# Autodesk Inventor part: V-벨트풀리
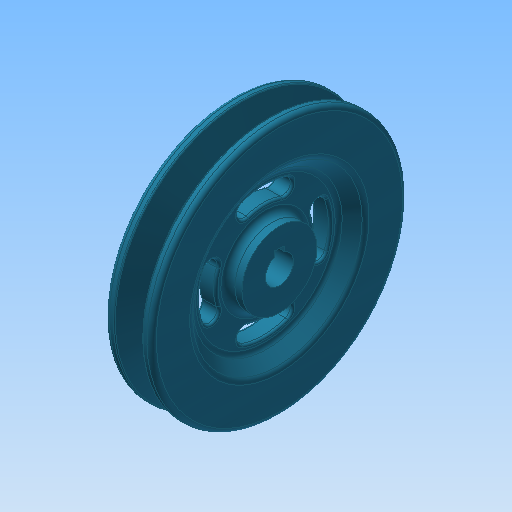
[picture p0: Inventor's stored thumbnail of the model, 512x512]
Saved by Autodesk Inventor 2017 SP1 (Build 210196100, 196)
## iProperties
Created: 2015-12
Part Number: V-벨트풀리
Document SubType Name: Modeling
Designer: mdu
Density: 8.08 g/cm^3
Material: 스테인리스강
Mass: 919.289 g
Surface Area: 326.109 cm^2
Volume: 113.773 cm^3
Appearance: 터키옥색
Author: mdu
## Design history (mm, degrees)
sketch "스케치1"
  geometry: L1 (-10, 0)-(10, 0); L2 (-10, 0)-(-10, 16); L3 (-10, 16)-(-4, 16); L4 (-4, 16)-(-4, 31); L5 (-4, 31)-(-10, 37); L6 (-10, 37)-(-10, 54.5); L7 (-10, 54.5)-(-5.976, 54.5); L8 (-5.976, 54.5)-(-2.154, 42); L9 (-2.154, 42)-(2.154, 42); L10 (2.154, 42)-(5.976, 54.5); L11 (5.976, 54.5)-(10, 54.5); L12 (10, 54.5)-(10, 37); L13 (10, 37)-(4, 31); L14 (4, 31)-(4, 16); L15 (4, 16)-(10, 16); L16 (10, 16)-(10, 0); L17 (-4.6, 50)-(4.6, 50); 2 further points
  constraints: 34 end point, 7 parallel, 6 equal length, 5 collinear, 3 perpendicular, 2 point on line, 1 coincident, 1 horizontal, 1 midpoint
  dimensions: "d0" = 20 distance of L1.start L1.end; "d1" = 9.2 distance of L17.start L17.end; "d2" = 34 deg angle of L10 L8; "d3" = 4.5 distance between parallel lines of L7 L17; "d4" = 8 distance between parallel lines of L9 L17; "d6" = 100 diameter of L17 L1; "d7" = 32 diameter of L3 L1; "d8" = 74 diameter of L5.end L1; "d9" = 6 distance of L2.end L3.end; "d10" = 135 deg angle of L4 L5
revolve "회전1" sketch "스케치1" stored, may be unused: angle "d11" = 90 deg
fillet "모깎기1" dims "d12" = 2, "d13" = 0.5, "d14" = 1, "d15" = 3
sketch "스케치2"
  geometry: L1 (-2, 5.657)-(-2, 7.8); L2 (-2, 7.8)-(2, 7.8); L3 (2, 7.8)-(2, 5.657); A1 r 6 centre (0, 0) between (-2, 5.657) and (2, 5.657); 1 further point
  constraints: 6 end point, 2 parallel, 2 point on circle, 1 centre point, 1 coincident, 1 perpendicular, 1 vertical
  dimensions: "d16" = 12 diameter of A1; "d17" = 4 distance of L1.end L2.end; "d18" = 13.8 dimension on A1 L2 (computed from d16)
extrude "돌출1" cut sketch "스케치2" stored distance "d19" = 10; taper "d20" = 0 deg
sketch "스케치3"
  geometry: L1 (0, 0)-(0, 24.5); L2 (0, 0)-(-8.379, 23.022); C1 r 29.757 at (0, 0) reference; C2 r 19 at (0, 0) reference; A1 r 24.5 centre (0, 0) between (0, 24.5) and (-8.379, 23.022); A2 r 3.3 centre (-8.379, 23.022) between (-9.508, 26.123) and (-7.251, 19.921); A3 r 3.3 centre (8.379, 23.022) between (7.251, 19.921) and (9.508, 26.123); A4 r 27.8 centre (0, 0) between (9.508, 26.123) and (-9.508, 26.123); A5 r 21.2 centre (0, 0) between (7.251, 19.921) and (-7.251, 19.921); 1 further point
  constraints: 10 point on circle, 5 centre point, 4 coincident, 4 end point, 1 point on line, 1 symmetric about line, 1 tangent, 1 vertical, 1 other
  dimensions: "d24" = 49 diameter of A1; "d27" = 20 deg angle of L1 L2; "d29" = 6.6 diameter of A2
extrude "돌출2" cut sketch "스케치3" stored distance "d30" = 10; taper "d31" = 0 deg
fillet "모깎기2" dims "d32" = 1
node "솔리드1"
pattern_circular "원형 패턴1" dims angle "d34" = 360 deg
